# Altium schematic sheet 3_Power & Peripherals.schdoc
size 309 x 223 mm; Symbol: Artery_A4; Device: Artery_A4; Company: Artery Technology; Drawed: SD; Version: 1.2; Page Size: A4; @Project Name: AT_START_F403A_V1.2; @Page Count: 4; @Update Date: 2023-09-05; @Schematic Name: AT_START_F403A; @Page No: 3; @Page Name: Power &amp; Peripherals
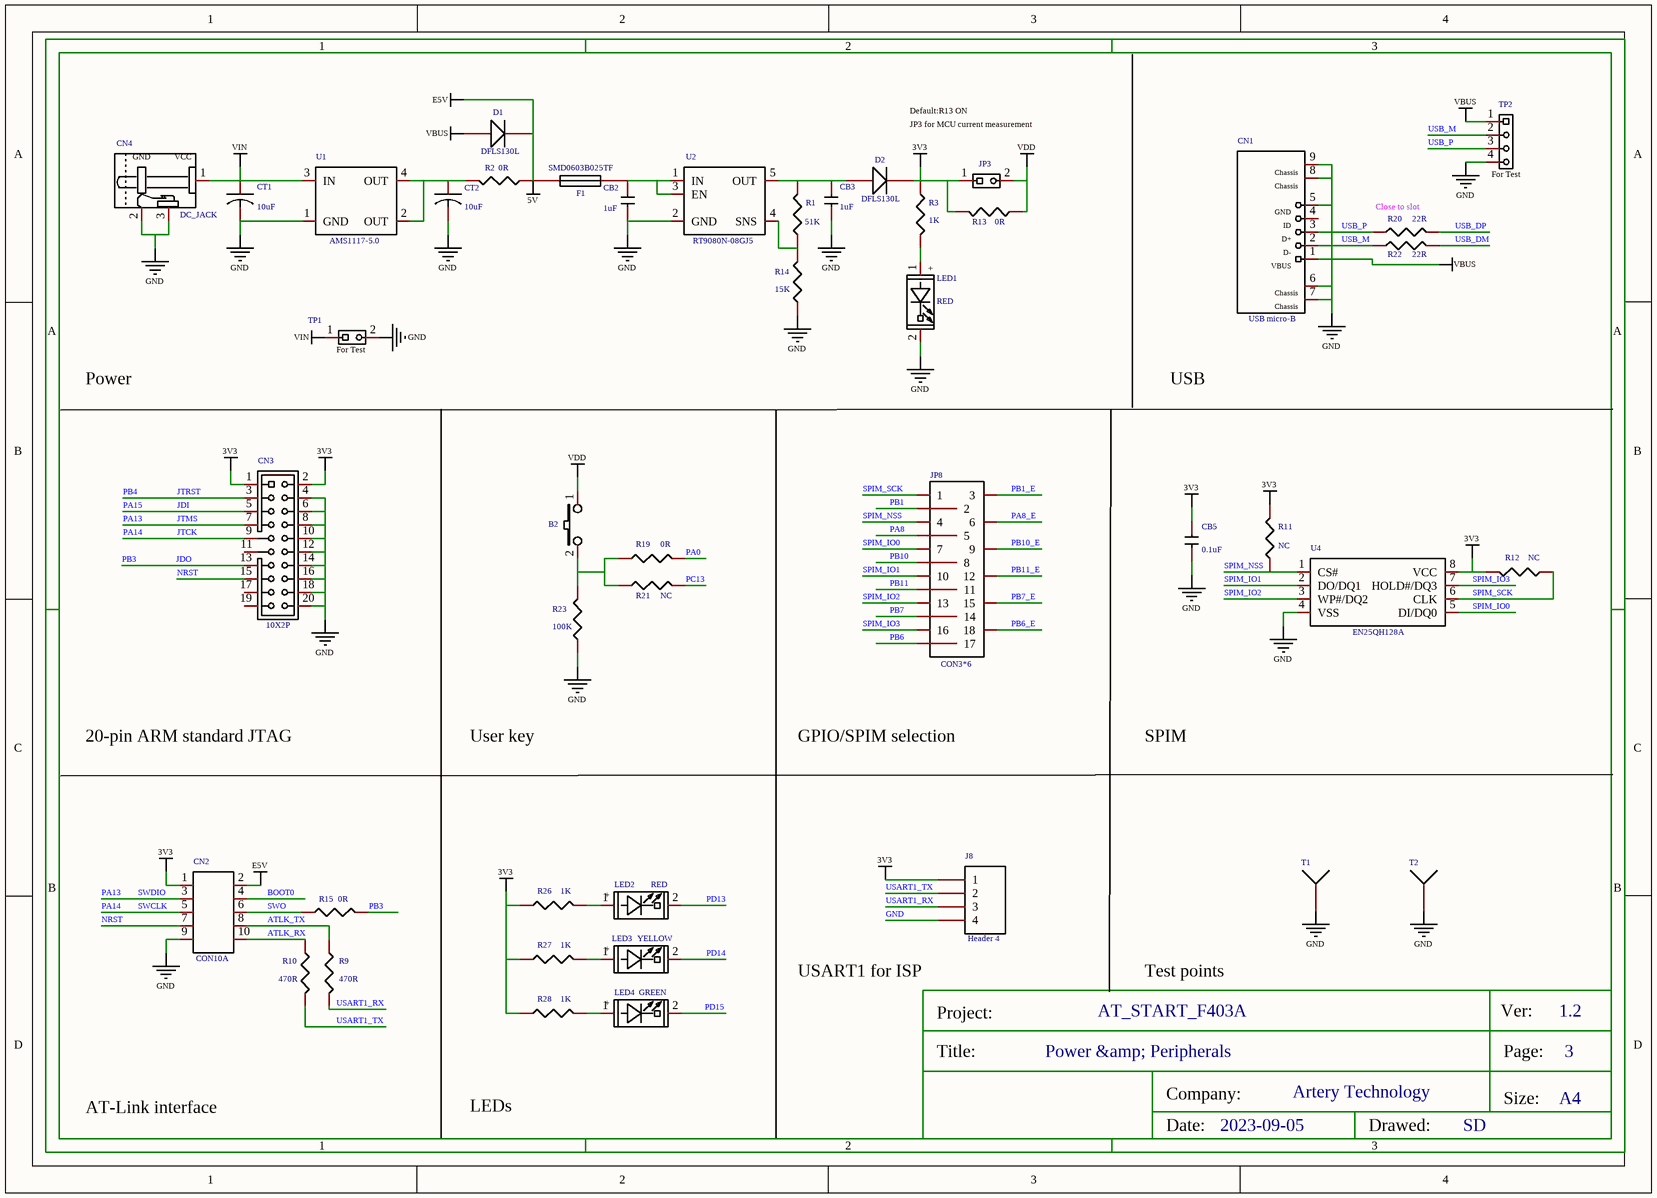
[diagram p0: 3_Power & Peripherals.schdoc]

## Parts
B2  PB,Blue,SMD_2P  [KEY_SOP_6*6]  (value not drawn)
CB2  1uF  [C0603]
CB3  1uF  [C0603]
CB5  0.1uF  [C0603]
CN1  USB micro-B  [USB_MIC_DIP]
CN2  CON10A  [HDR2X5]
CN3  10X2P  [JTAG_20]
CN4  DC_JACK  [DC10B]
CT1  10uF  [C3528]
CT2  10uF  [C3528]
D1  DFLS130L  [SOD-123]
D2  DFLS130L  [SOD-123]
F1  SMD0603B025TF  [r0603]
J8  Header 4  [HDR1X4]
JP3  1X2P_2.54M  [HDR1X2]  (value not drawn)
JP8  CON3*6  [HDR3X6]
LED1  RED  [LED0603]
LED2  RED  [LED0603]
LED3  YELLOW  [LED0603]
LED4  GREEN  [LED0603]
R1  51K  [r0603]
R2  0R  [SB-PAD]
R3  1K  [r0603]
R9  470R  [0603_R]
R10  470R  [0603_R]
R11  NC  [r0603]
R12  NC  [r0603]
R13  0R  [SB-PAD]
R14  15K  [r0603]
R15  0R  [SB-PAD]
R19  0R  [SB-PAD]
R20  22R  [r0603]
R21  NC  [SB-PAD]
R22  22R  [r0603]
R23  100K  [r0603]
R26  1K  [r0603]
R27  1K  [r0603]
R28  1K  [r0603]
T1  Socket  [TestPoint]  (value not drawn)
T2  Socket  [TestPoint]  (value not drawn)
TP1  1X2P_2.54M  [HDR1X2]  (value not drawn)
TP2  1X4P_2.54F  [HDR1X4 - top]  (value not drawn)
U1  AMS1117-5.0  [SOT223]
U2  RT9080N-08GJ5  [SOT-23-5]
U4  EN25QH128A  [SOIC8_208]

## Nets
3V3: CB5.1 CN2.1 CN3.1 CN3.2 D2.2(K) J8.1 JP3.1 R3.1 R11.2 R12.2 R13.2 R26.1 R27.1 R28.1 U4.8(VCC)
5V: CN2.2 D1.2(K) F1.1 R2.1  [also labelled E5V]
GND: CB2.2 CB3.2 CB5.2 CN1.5(GND) CN1.6 CN1.7 CN1.8 CN1.9 CN2.9 CN3.4 CN3.6 CN3.8 CN3.10 CN3.12 CN3.14 CN3.16 CN3.18 CN3.20 CN4.2 CN4.3 CT1.2 CT2.2 J8.4 LED1.2(CATHODE) R14.1 R23.1 T1.1 T2.1 TP1.2 TP2.4 U1.1(GND) U2.2(GND) U4.4(VSS)
VBUS: CN1.1(VBUS) D1.1(A) TP2.1
VDD: B2.1 JP3.2 R13.1
VIN: CN4.1 CT1.1 TP1.1 U1.3(IN)
ATLK_RX: CN2.10 R10.1
ATLK_TX: CN2.8 R9.1
BOOT0: CN2.4
JDI: CN3.5  [also labelled PA15]
JDO: CN3.13 R15.2  [also labelled PB3]
JTCK: CN2.5 CN3.9  [also labelled PA14, SWCLK]
JTMS: CN2.3 CN3.7  [also labelled PA13, SWDIO]
JTRST: CN3.3  [also labelled PB4]
NRST: CN2.7 CN3.15
PA0: R19.2
PA8: JP8.5
PA8_E: JP8.6
PB1: JP8.2
PB1_E: JP8.3
PB6: JP8.17
PB6_E: JP8.18
PB7: JP8.14
PB7_E: JP8.15
PB10: JP8.8
PB10_E: JP8.9
PB11: JP8.11
PB11_E: JP8.12
PC13: R21.2
PD13: LED2.2(CATHODE)
PD14: LED3.2(CATHODE)
PD15: LED4.2(CATHODE)
SPIM_IO0: JP8.7 U4.5(DI/DQ0)
SPIM_IO1: JP8.10 U4.2(DO/DQ1)
SPIM_IO2: JP8.13 U4.3(WP#/DQ2)
SPIM_IO3: JP8.16 U4.7(HOLD#/DQ3)
SPIM_NSS: JP8.4 R11.1 U4.1(CS#)
SPIM_SCK: JP8.1 R12.1 U4.6(CLK)
SWO: CN2.6 R15.1
USART1_RX: J8.3 R9.2
USART1_TX: J8.2 R10.2
USB_DM: R22.2
USB_DP: R20.2
USB_M: CN1.2(D-) R22.1 TP2.2
USB_P: CN1.3(D+) R20.1 TP2.3
NetB2_2: B2.2 R19.1 R21.1 R23.2
NetCB2_1: CB2.1 F1.2 U2.1(IN) U2.3(EN)
NetCB3_1: CB3.1 D2.1(A) R1.2 U2.5(OUT)
NetCT2_1: CT2.1 R2.2 U1.2(OUT) U1.4(OUT)
NetLED1_1: LED1.1(ANODE) R3.2
NetLED2_1: LED2.1(ANODE) R26.2
NetLED3_1: LED3.1(ANODE) R27.2
NetLED4_1: LED4.1(ANODE) R28.2
NetR1_1: R1.1 R14.2 U2.4(SNS)

Not connected (* = marked no-connect by the designer): CN1 4(ID); CN3 11 17 19

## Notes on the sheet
- JP3 for MCU current measurement
- Default:R13 ON
- Close to slot
- (near TP2) For Test
- Power
- (near TP1) For Test
- USB
- 20-pin ARM standard JTAG
- User key
- GPIO/SPIM selection
- SPIM
- USART1 for ISP
- Test points
- AT-Link interface
- LEDs

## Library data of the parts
B2 = PB,Blue,SMD_2P: Symbol: Push_Bottom,Blue,SMD_2P; Add into BOM: yes
CB2 CB3 = 1uF: Symbol: 0.1uF,50V,20%,SMD0603; Add into BOM: yes
CB5 = 0.1uF: Symbol: 10uF,10V,10%,SMD0603; Add into BOM: yes
CN1 = USB micro-B: Symbol: USB_miniAB,SMD_0; Add into BOM: yes
CN2 = CON10A: Symbol: CON10A_0; Add into BOM: yes
CN3 = 10X2P: Symbol: 10x2P,Male,Housing,DIP_2.54; Add into BOM: yes
CN4 = DC_JACK: Symbol: DC12V_Power_JACK,2.0,DIP_3P; Add into BOM: yes
CT1 CT2 = 10uF: 10uF,10%,25V; Symbol: 10uF,16V,20%,B_Case_Dup1; Add into BOM: yes
D1 D2 = DFLS130L: Default Diode; Add into BOM: yes
F1 = SMD0603B025TF: Fuse; Symbol: Fuse 1; Add into BOM: yes
J8 = Header 4: Header, 4-Pin; Add into BOM: yes
JP3 = 1X2P_2.54M: Symbol: 1X2P,Male,DIP_2.54; Origin Footprint 2: SIP_2P; Add into BOM: yes
JP8 = CON3*6: Add into BOM: yes
LED1 LED2 = RED: Symbol: RED,SMD0603; Add into BOM: yes
LED3 = YELLOW: Symbol: YELLOW,SMD0603; Add into BOM: yes
LED4 = GREEN: Symbol: GREEN,SMD0603; Add into BOM: yes
R1 = 51K: Symbol: 470,1/10W,1%,SMD0603; Add into BOM: yes
R2 R13 R15 R19 = 0R: Symbol: 470,1/10W,1%,SMD0603; Add into BOM: yes
R3 R26-R28 = 1K: Symbol: 470,1/10W,1%,SMD0603; Add into BOM: yes
R9 R10 = 470R: Symbol: 470,1/10W,1%,SMD0603; Add into BOM: yes
R11 R12 = NC: Symbol: 47K,1/10W,1%,SMD0603; Add into BOM: yes
R14 = 15K: Symbol: 470,1/10W,1%,SMD0603; Add into BOM: yes
R20 R22 = 22R: Symbol: 22,1/10W,1%,SMD0603; Add into BOM: yes
R21 = NC: Symbol: 470,1/10W,1%,SMD0603; Add into BOM: yes
R23 = 100K: Symbol: 10K,1/10W,1%,SMD0603; Add into BOM: yes
T1 T2 = Socket: Add into BOM: yes
TP1 = 1X2P_2.54M: Symbol: 1X2P,Male,DIP_2.54; Origin Footprint 2: SIP_2P; Add into BOM: yes; Origin Footprint 1: HDR1X2 - SOP
TP2 = 1X4P_2.54F: Symbol: 1X4P,Female,DIP_2.54; Origin Footprint 2: SIP_4P; Add into BOM: yes
U1 = AMS1117-5.0: Symbol: AMS1117-3.3; Add into BOM: yes
U2 = RT9080N-08GJ5: Add into BOM: yes
U4 = EN25QH128A: Symbol: W25Q128FVSIQ,SOIC8_1; Add into BOM: yes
